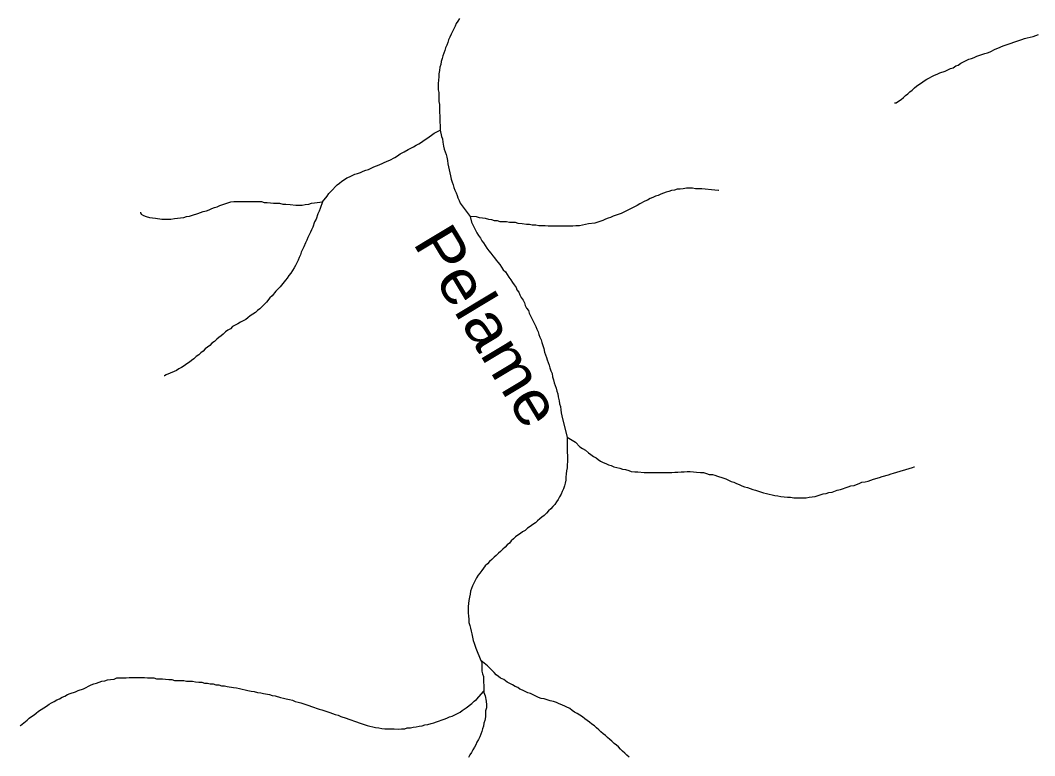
# Model space of a CAD drawing. Extents: x 652.3 to 678, y 7316.9 to 7344.9.
# Drawn here: x 658.957 to 660.791, y 7325.012 to 7326.342 of the extents above; entities that cross this region are included whole.
import ezdxf
from ezdxf.enums import TextEntityAlignment as Align

# ---------------------------------------------------------------- set-up
doc = ezdxf.new("R2010")
doc.units = 0
doc.header["$LTSCALE"] = 0.032
doc.layers.add('61', color=7, linetype='Continuous')
doc.layers.add('7', color=7, linetype='Continuous', lineweight=25)

msp = doc.modelspace()

# ---------------------------------------------------------------- linework, layer by layer
at = {"layer": '7'}
for points in [[(659.7517, 7326.3451), (659.7485, 7326.3403), (659.7454, 7326.3356), (659.7438, 7326.3308), (659.7414, 7326.326), (659.739, 7326.3212), (659.7366, 7326.3165), (659.7342, 7326.3109), (659.7318, 7326.3061), (659.7302, 7326.3013), (659.7287, 7326.2966), (659.7263, 7326.2918), (659.7247, 7326.287), (659.7231, 7326.2823), (659.7215, 7326.2775), (659.7199, 7326.2727), (659.7183, 7326.2671), (659.7175, 7326.2616), (659.7159, 7326.2568), (659.7151, 7326.2512), (659.7143, 7326.2449), (659.7143, 7326.2393), (659.7135, 7326.2337), (659.7127, 7326.2274), (659.7127, 7326.2218), (659.7127, 7326.2162), (659.7143, 7326.2114), (659.7143, 7326.2059), (659.7143, 7326.2003), (659.7143, 7326.1947), (659.7151, 7326.1892), (659.7151, 7326.1836), (659.7151, 7326.178), (659.7159, 7326.1661), (659.7167, 7326.143)], [(660.5379, 7326.1923), (660.5411, 7326.1923), (660.545, 7326.1955), (660.5498, 7326.1987), (660.5538, 7326.2019), (660.5578, 7326.2059), (660.5617, 7326.209), (660.5657, 7326.2122), (660.5697, 7326.2154), (660.5737, 7326.2194), (660.5777, 7326.2226), (660.5816, 7326.2258), (660.5864, 7326.2289), (660.5912, 7326.2321), (660.596, 7326.2353), (660.6103, 7326.2425), (660.6151, 7326.2441), (660.6198, 7326.2464), (660.6294, 7326.2496), (660.6389, 7326.2544), (660.6437, 7326.256), (660.6485, 7326.2592), (660.6532, 7326.2608), (660.658, 7326.264), (660.6628, 7326.2663), (660.6723, 7326.2711), (660.6771, 7326.2727), (660.6819, 7326.2743), (660.6867, 7326.2767), (660.701, 7326.2815), (660.7058, 7326.283), (660.7105, 7326.2846), (660.7201, 7326.2894), (660.7249, 7326.291), (660.7344, 7326.2958), (660.7487, 7326.3006), (660.7535, 7326.3021), (660.7678, 7326.3069), (660.7726, 7326.3085), (660.7774, 7326.3101), (660.7829, 7326.3109), (660.7885, 7326.3125), (660.7981, 7326.3157)], [(659.5035, 7326.0133), (659.5122, 7326.0237), (659.5154, 7326.0284), (659.5186, 7326.0324), (659.5305, 7326.0443), (659.5345, 7326.0475), (659.5385, 7326.0507), (659.5433, 7326.0539), (659.548, 7326.0571), (659.5528, 7326.0587), (659.5624, 7326.0634), (659.5671, 7326.065), (659.5727, 7326.0666), (659.5775, 7326.069), (659.5822, 7326.0706), (659.587, 7326.0722), (659.5966, 7326.077), (659.6061, 7326.0801), (659.6204, 7326.0873), (659.6252, 7326.0889), (659.6348, 7326.0937), (659.6395, 7326.0969), (659.6443, 7326.1), (659.6515, 7326.104), (659.6586, 7326.108), (659.6682, 7326.1128), (659.673, 7326.116), (659.6777, 7326.1183), (659.6825, 7326.1215), (659.6873, 7326.1247), (659.6921, 7326.1279), (659.6968, 7326.1311), (659.7008, 7326.1343), (659.7056, 7326.1374), (659.7167, 7326.143)], [(659.7167, 7326.143), (659.7191, 7326.1319), (659.7207, 7326.1271), (659.7215, 7326.1215), (659.7223, 7326.1144), (659.7239, 7326.1088), (659.7255, 7326.104), (659.7271, 7326.0992), (659.7287, 7326.0945), (659.7295, 7326.0881), (659.7302, 7326.0825), (659.7318, 7326.077), (659.7326, 7326.0714), (659.7342, 7326.0658), (659.735, 7326.0603), (659.7366, 7326.0547), (659.7382, 7326.0491), (659.7398, 7326.0443), (659.7414, 7326.0396), (659.743, 7326.0348)], [(659.743, 7326.0348), (659.7454, 7326.03), (659.747, 7326.0252), (659.7485, 7326.0205), (659.7509, 7326.0157), (659.7525, 7326.0109), (659.7708, 7325.9871)], [(660.2204, 7326.0341), (660.2196, 7326.0342), (660.2132, 7326.0348), (660.1894, 7326.0372), (660.1782, 7326.0372), (660.1726, 7326.038), (660.1615, 7326.038), (660.1559, 7326.0372), (660.1504, 7326.0364), (660.1448, 7326.0364), (660.14, 7326.0348), (660.1345, 7326.034), (660.1297, 7326.0324), (660.1249, 7326.0308), (660.1154, 7326.0276), (660.1106, 7326.0252), (660.1058, 7326.0237), (660.101, 7326.0213), (660.0963, 7326.0197), (660.0915, 7326.0165), (660.0867, 7326.0149), (660.0772, 7326.0101), (660.0724, 7326.0069), (660.0437, 7325.9926), (660.0294, 7325.9878), (660.0247, 7325.9855), (660.0199, 7325.9839), (660.0151, 7325.9823), (660.0103, 7325.9799), (659.996, 7325.9751), (659.9849, 7325.9735), (659.9793, 7325.9727), (659.9737, 7325.9711), (659.9682, 7325.9703), (659.9618, 7325.9703), (659.9562, 7325.9695), (659.9117, 7325.9695), (659.9061, 7325.9703), (659.895, 7325.9703), (659.8894, 7325.9711), (659.883, 7325.9711), (659.8782, 7325.9727), (659.8727, 7325.9727), (659.8647, 7325.9735), (659.8576, 7325.9743), (659.8528, 7325.9759), (659.8416, 7325.9759), (659.8361, 7325.9775), (659.8249, 7325.9775), (659.8202, 7325.9791), (659.8146, 7325.9791), (659.8098, 7325.9807), (659.8042, 7325.9815), (659.7987, 7325.9831), (659.7931, 7325.9839), (659.7875, 7325.9847), (659.782, 7325.9863), (659.7708, 7325.9871)], [(659.1748, 7325.9946), (659.1749, 7325.9942), (659.1757, 7325.991), (659.1804, 7325.9886), (659.1852, 7325.9871), (659.1908, 7325.9855), (659.1963, 7325.9847), (659.2019, 7325.9839), (659.213, 7325.9823), (659.2298, 7325.9823), (659.2361, 7325.9831), (659.2417, 7325.9839), (659.2473, 7325.9847), (659.2528, 7325.9855), (659.2576, 7325.9871), (659.2632, 7325.9878), (659.2687, 7325.9894), (659.2783, 7325.9926), (659.2831, 7325.9942), (659.2878, 7325.9958), (659.2942, 7325.9974), (659.299, 7325.999), (659.3038, 7326.0014), (659.3085, 7326.003), (659.3133, 7326.0046), (659.3181, 7326.0069), (659.3324, 7326.0117), (659.338, 7326.0133), (659.3435, 7326.0141), (659.3937, 7326.0141), (659.3984, 7326.0125), (659.404, 7326.0125), (659.4096, 7326.0117), (659.4152, 7326.0109), (659.4263, 7326.0109), (659.4319, 7326.0093), (659.4374, 7326.0093), (659.4454, 7326.0085), (659.4557, 7326.0077), (659.4669, 7326.0077), (659.4724, 7326.0085), (659.4788, 7326.0093), (659.4836, 7326.0109), (659.4892, 7326.0117), (659.5035, 7326.0133)], [(659.5035, 7326.0133), (659.4995, 7326.0014), (659.4979, 7325.9966), (659.4955, 7325.9918), (659.4923, 7325.9823), (659.4892, 7325.9775), (659.486, 7325.968), (659.4836, 7325.9632), (659.482, 7325.9584), (659.4772, 7325.9489), (659.4756, 7325.9441), (659.4732, 7325.9393), (659.4701, 7325.9322), (659.4653, 7325.9226), (659.4637, 7325.9178), (659.4613, 7325.9131), (659.4597, 7325.9083), (659.4573, 7325.9035), (659.4549, 7325.8987), (659.4526, 7325.894), (659.4462, 7325.8844), (659.443, 7325.8804), (659.4398, 7325.8757), (659.4366, 7325.8717), (659.4271, 7325.8597), (659.4191, 7325.8518), (659.4128, 7325.8438), (659.4088, 7325.8399), (659.4024, 7325.8319), (659.3905, 7325.82), (659.3865, 7325.8168), (659.3825, 7325.8136), (659.3778, 7325.8104), (659.373, 7325.8072), (659.369, 7325.804), (659.365, 7325.8009), (659.3555, 7325.7961), (659.3507, 7325.7929), (659.3412, 7325.7881), (659.3372, 7325.7842), (659.3324, 7325.7818), (659.3284, 7325.7786), (659.3244, 7325.7746), (659.3205, 7325.7714), (659.3165, 7325.7682), (659.3125, 7325.7651), (659.3085, 7325.7611), (659.3038, 7325.7579), (659.2998, 7325.7539), (659.2958, 7325.7507), (659.2918, 7325.7476), (659.2878, 7325.7436), (659.2839, 7325.7404), (659.2799, 7325.7372), (659.2751, 7325.734), (659.2711, 7325.73), (659.2672, 7325.7269), (659.2632, 7325.7237), (659.2584, 7325.7205), (659.2536, 7325.7173), (659.2489, 7325.7141), (659.2441, 7325.7117), (659.2401, 7325.7086), (659.2353, 7325.707), (659.221, 7325.7006), (659.2181, 7325.6993), (659.2177, 7325.6992)], [(659.7708, 7325.9871), (659.7732, 7325.9767), (659.7756, 7325.9719), (659.778, 7325.9672), (659.7804, 7325.9624), (659.7828, 7325.9576), (659.7859, 7325.9528), (659.7891, 7325.9481), (659.7915, 7325.9433), (659.7947, 7325.9393), (659.7979, 7325.9345), (659.8011, 7325.9298), (659.8042, 7325.925), (659.8082, 7325.921), (659.8114, 7325.9162), (659.8146, 7325.9123), (659.8178, 7325.9083), (659.821, 7325.9043), (659.8241, 7325.9003), (659.8273, 7325.8955), (659.8305, 7325.8908), (659.8345, 7325.8868), (659.8377, 7325.882), (659.8408, 7325.8772), (659.844, 7325.8725), (659.8472, 7325.8677), (659.8504, 7325.8637), (659.8536, 7325.8589), (659.8552, 7325.8542), (659.8584, 7325.8502), (659.8607, 7325.8454), (659.8631, 7325.8406), (659.8663, 7325.8359), (659.8687, 7325.8311), (659.8703, 7325.8263), (659.8727, 7325.8215), (659.8759, 7325.8168), (659.8774, 7325.812), (659.8798, 7325.8072), (659.8822, 7325.8025), (659.8846, 7325.7977), (659.887, 7325.7929), (659.8894, 7325.7881), (659.891, 7325.7834), (659.8934, 7325.7786), (659.895, 7325.7738), (659.8965, 7325.769), (659.8989, 7325.7643), (659.9005, 7325.7595), (659.9021, 7325.7539), (659.9037, 7325.7483), (659.9053, 7325.742), (659.9069, 7325.7372), (659.9085, 7325.7324), (659.9101, 7325.7277), (659.9117, 7325.7229), (659.9133, 7325.7181), (659.9148, 7325.7133), (659.9164, 7325.7078), (659.9188, 7325.703), (659.9196, 7325.6974), (659.9212, 7325.6919), (659.9228, 7325.6863), (659.9244, 7325.6815), (659.926, 7325.6767), (659.9276, 7325.6712), (659.9292, 7325.6664), (659.93, 7325.6608), (659.9316, 7325.6537), (659.9324, 7325.6481), (659.9339, 7325.6433), (659.9347, 7325.6377), (659.9355, 7325.6322), (659.9363, 7325.6266), (659.9387, 7325.6163), (659.9459, 7325.5884)], [(659.9459, 7325.5884), (659.9459, 7325.5773), (659.9459, 7325.5717), (659.9459, 7325.5661), (659.9459, 7325.5606), (659.9467, 7325.555), (659.9467, 7325.5494), (659.9467, 7325.5439), (659.9459, 7325.5383), (659.9459, 7325.5327), (659.9451, 7325.5271), (659.9443, 7325.5216), (659.9435, 7325.516), (659.9435, 7325.5104), (659.9427, 7325.5049), (659.9411, 7325.5001), (659.9395, 7325.4945), (659.9371, 7325.4897), (659.9355, 7325.485), (659.9324, 7325.4802)], [(659.9459, 7325.5884), (659.961, 7325.5789), (659.969, 7325.5709), (659.9737, 7325.5677), (659.9793, 7325.5645), (659.9849, 7325.5598), (659.9888, 7325.5566), (659.9936, 7325.5534), (659.9984, 7325.551), (660.0024, 7325.5478), (660.0064, 7325.5446), (660.0111, 7325.5423), (660.0159, 7325.5407), (660.0207, 7325.5383), (660.0254, 7325.5367), (660.0302, 7325.5343), (660.0358, 7325.5335), (660.0414, 7325.5319), (660.0461, 7325.5303), (660.0517, 7325.5295), (660.0573, 7325.5279), (660.062, 7325.5263), (660.0684, 7325.5256), (660.074, 7325.5256), (660.0851, 7325.524), (660.1353, 7325.524), (660.1408, 7325.5248), (660.1464, 7325.5248), (660.152, 7325.5256), (660.1575, 7325.5256), (660.1631, 7325.5263), (660.1687, 7325.5263), (660.1742, 7325.5256), (660.1798, 7325.5248), (660.187, 7325.524), (660.1925, 7325.524), (660.1981, 7325.5224), (660.2029, 7325.5208), (660.2085, 7325.5208), (660.2132, 7325.5192), (660.218, 7325.5176), (660.2276, 7325.5144), (660.2331, 7325.5128), (660.2427, 7325.508), (660.2474, 7325.5065), (660.2522, 7325.5041), (660.257, 7325.5025), (660.2618, 7325.5001), (660.2665, 7325.4985), (660.2721, 7325.4969), (660.2817, 7325.4937), (660.2864, 7325.4921), (660.3008, 7325.4874), (660.3063, 7325.4866), (660.3111, 7325.485), (660.3167, 7325.4842), (660.3214, 7325.4826), (660.327, 7325.4818), (660.3326, 7325.481), (660.3382, 7325.4802), (660.3445, 7325.4794), (660.3501, 7325.4794), (660.3557, 7325.4786), (660.3779, 7325.4786), (660.3835, 7325.4794), (660.3946, 7325.481), (660.409, 7325.4858), (660.4145, 7325.4866), (660.4193, 7325.4882), (660.4249, 7325.489), (660.4344, 7325.4921), (660.44, 7325.4937), (660.4543, 7325.4985), (660.4591, 7325.5001), (660.4647, 7325.5009), (660.4694, 7325.5025), (660.4742, 7325.5041), (660.479, 7325.5065), (660.4846, 7325.5073), (660.4901, 7325.5088), (660.4949, 7325.5104), (660.4997, 7325.512), (660.5108, 7325.5152), (660.5156, 7325.5168), (660.5267, 7325.52), (660.5315, 7325.5216), (660.5363, 7325.5232), (660.5705, 7325.5335), (660.5735, 7325.5344), (660.5739, 7325.5345)], [(659.9324, 7325.4802), (659.93, 7325.4754), (659.9268, 7325.4714), (659.9236, 7325.4667), (659.9204, 7325.4627), (659.9164, 7325.4587), (659.9125, 7325.4547), (659.9085, 7325.4508), (659.9045, 7325.4468), (659.9005, 7325.4436), (659.8965, 7325.4404), (659.8926, 7325.4372), (659.8886, 7325.4333), (659.8838, 7325.4301), (659.879, 7325.4269), (659.8743, 7325.4237), (659.8703, 7325.4197), (659.8655, 7325.4173), (659.8615, 7325.4142), (659.8568, 7325.411), (659.8528, 7325.4078), (659.8488, 7325.4046), (659.8448, 7325.4006), (659.8416, 7325.3967), (659.8377, 7325.3935), (659.8337, 7325.3895), (659.8297, 7325.3855), (659.8257, 7325.3815), (659.8218, 7325.3784), (659.8178, 7325.3744), (659.8138, 7325.3712), (659.8098, 7325.3672), (659.8058, 7325.3632), (659.8019, 7325.3593), (659.7979, 7325.3553), (659.7947, 7325.3513), (659.7915, 7325.3473), (659.7883, 7325.3425), (659.7851, 7325.3386), (659.782, 7325.3338), (659.7796, 7325.329), (659.7772, 7325.3242), (659.7748, 7325.3195), (659.7732, 7325.3147), (659.7716, 7325.3099), (659.7708, 7325.3044), (659.7692, 7325.2988), (659.7684, 7325.2932), (659.7676, 7325.2876), (659.7668, 7325.2821), (659.7668, 7325.2765), (659.7668, 7325.2709), (659.7676, 7325.2646), (659.7684, 7325.259), (659.7684, 7325.2534), (659.77, 7325.2479), (659.7716, 7325.2431), (659.7724, 7325.2375), (659.774, 7325.2327), (659.7748, 7325.2264), (659.7764, 7325.2208), (659.778, 7325.216), (659.7812, 7325.2065), (659.7902, 7325.1843)], [(659.8942, 7325.1174), (659.8798, 7325.1245), (659.8751, 7325.1261), (659.8655, 7325.1309), (659.8607, 7325.1325), (659.8568, 7325.1357), (659.852, 7325.1373), (659.8472, 7325.1404), (659.8377, 7325.1452), (659.8313, 7325.15), (659.8257, 7325.1524), (659.8218, 7325.1556), (659.8178, 7325.1587), (659.8138, 7325.1627), (659.8019, 7325.1747), (659.7902, 7325.1843)], [(659.7902, 7325.1843), (659.7915, 7325.181), (659.7915, 7325.1651), (659.7931, 7325.1603), (659.7947, 7325.1556), (659.7954, 7325.1292)], [(658.9574, 7325.0663), (658.958, 7325.0668), (658.964, 7325.072), (658.9696, 7325.0768), (658.9735, 7325.08), (658.9775, 7325.0832), (658.9823, 7325.0863), (658.9863, 7325.0895), (658.9903, 7325.0927), (658.995, 7325.0959), (658.9998, 7325.0991), (659.0046, 7325.1022), (659.0094, 7325.1054), (659.0141, 7325.1078), (659.0189, 7325.1102), (659.0237, 7325.1134), (659.0284, 7325.115), (659.0332, 7325.1182), (659.038, 7325.1198), (659.0428, 7325.1229), (659.0475, 7325.1245), (659.0571, 7325.1277), (659.0619, 7325.1301), (659.0714, 7325.1333), (659.0857, 7325.1404), (659.0905, 7325.142), (659.0953, 7325.1436), (659.1048, 7325.1468), (659.1104, 7325.1476)], [(659.1104, 7325.1476), (659.1152, 7325.1492), (659.1207, 7325.15), (659.1271, 7325.1508), (659.1319, 7325.1532), (659.1486, 7325.1532), (659.1542, 7325.154), (659.182, 7325.154), (659.1876, 7325.1532), (659.1987, 7325.1532), (659.2035, 7325.1516), (659.2146, 7325.1516), (659.2202, 7325.1508), (659.2258, 7325.15), (659.2313, 7325.15), (659.2361, 7325.1484), (659.2528, 7325.1484), (659.2576, 7325.1468), (659.2687, 7325.1468), (659.2743, 7325.146), (659.2799, 7325.1452), (659.2855, 7325.1452), (659.2902, 7325.1436), (659.2958, 7325.1436), (659.3006, 7325.142), (659.3061, 7325.142), (659.3109, 7325.1404), (659.3165, 7325.1404), (659.3213, 7325.1388), (659.3268, 7325.1388), (659.3316, 7325.1373), (659.3427, 7325.1357), (659.3483, 7325.1349), (659.3539, 7325.1341), (659.3587, 7325.1325), (659.3642, 7325.1317), (659.369, 7325.1301), (659.3746, 7325.1293), (659.3801, 7325.1285), (659.3865, 7325.1269), (659.3921, 7325.1261), (659.3969, 7325.1245), (659.408, 7325.1229), (659.4128, 7325.1213), (659.4183, 7325.1205), (659.4279, 7325.1174), (659.4335, 7325.1166), (659.4382, 7325.115), (659.4438, 7325.1142), (659.4494, 7325.1126), (659.4541, 7325.1102), (659.4597, 7325.1094), (659.4645, 7325.1078), (659.4788, 7325.103), (659.4836, 7325.1015), (659.4979, 7325.0967), (659.5027, 7325.0951), (659.517, 7325.0903), (659.5218, 7325.0887), (659.5266, 7325.0871), (659.5321, 7325.0855), (659.5369, 7325.0832), (659.5464, 7325.08), (659.5512, 7325.0784), (659.5655, 7325.0736), (659.5703, 7325.072), (659.5846, 7325.0672), (659.5894, 7325.0656), (659.595, 7325.0648), (659.5998, 7325.0633), (659.6053, 7325.0625), (659.6109, 7325.0617), (659.6165, 7325.0609), (659.6332, 7325.0609), (659.6403, 7325.0601), (659.6467, 7325.0609), (659.6523, 7325.0609), (659.657, 7325.0625), (659.6626, 7325.0625), (659.6674, 7325.0641), (659.673, 7325.0648), (659.6785, 7325.0656), (659.6841, 7325.0664), (659.6889, 7325.068), (659.6944, 7325.0688), (659.7, 7325.0704), (659.7048, 7325.072), (659.7096, 7325.0736), (659.7239, 7325.0784), (659.7287, 7325.08), (659.7334, 7325.0824), (659.7382, 7325.0839), (659.743, 7325.0863), (659.7478, 7325.0887), (659.7525, 7325.0911), (659.7565, 7325.0943), (659.7637, 7325.0991), (659.774, 7325.107), (659.778, 7325.111), (659.782, 7325.1142), (659.7954, 7325.1292)], [(659.7954, 7325.1292), (659.7955, 7325.1269), (659.7979, 7325.1205), (659.7995, 7325.111), (659.8003, 7325.1046), (659.8003, 7325.0991), (659.7987, 7325.0935), (659.7987, 7325.0879), (659.7987, 7325.0824), (659.7971, 7325.076), (659.7955, 7325.0712), (659.7947, 7325.0656), (659.7931, 7325.0609), (659.7915, 7325.0561), (659.7899, 7325.0513), (659.7883, 7325.0465), (659.7859, 7325.0418), (659.7828, 7325.037), (659.7812, 7325.0322), (659.7788, 7325.0275), (659.7756, 7325.0227), (659.7732, 7325.0179), (659.77, 7325.0139), (659.7676, 7325.0092)], [(660.0581, 7325.0099), (660.0541, 7325.0131), (660.0501, 7325.0171), (660.0461, 7325.0203), (660.0422, 7325.0243), (660.039, 7325.0282), (660.035, 7325.0314), (660.031, 7325.0346), (660.027, 7325.0386), (660.0231, 7325.0418), (660.0191, 7325.045), (660.0151, 7325.0489), (660.0111, 7325.0521), (660.0071, 7325.0553), (660.0032, 7325.0593), (659.9992, 7325.0625), (659.9952, 7325.0664), (659.9904, 7325.0696), (659.9865, 7325.0728), (659.9825, 7325.076), (659.9777, 7325.0792), (659.9737, 7325.0824), (659.969, 7325.0855), (659.9642, 7325.0887), (659.9594, 7325.0911), (659.9554, 7325.0943), (659.9507, 7325.0975), (659.9363, 7325.1046), (659.9316, 7325.1062), (659.9268, 7325.1086), (659.9212, 7325.1102), (659.9156, 7325.1118), (659.9045, 7325.115), (659.8989, 7325.1158), (659.8942, 7325.1174)]]:
    msp.add_lwpolyline(points, dxfattribs=at)

# ---------------------------------------------------------------- texts
at = {"layer": '61', "width": 1.1}
msp.add_text('Pelame', height=0.08, rotation=301.03, dxfattribs=at).set_placement((659.7688, 7325.7688), align=Align.CENTER)

doc.saveas('drawing.dxf')
